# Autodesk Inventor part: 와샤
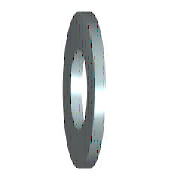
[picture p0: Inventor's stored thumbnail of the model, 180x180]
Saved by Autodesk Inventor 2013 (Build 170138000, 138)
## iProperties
IsCustomPart: 0
Created: 2009-02
Part Number: 와샤
Material: 강, 연강
Description: 평면 와셔
Document SubType Name: Modeling
Standard: KS B 1326
Designer: 한국산업디자인학원
Standards Organization: KS
Language: ko-KR
Size Designation: 5x10
Categories: <MemberInstance><Categories><Category DisplayName="조임쇠" InternalName="e4da775c-781d-43d5-af7c-5136215cf5a6" Mnemonic="FSTN"><Category DisplayName="와셔" InternalN
Density: 1 g/cm^3
Author: 한국산업디자인학원
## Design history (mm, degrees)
sketch "스케치"
  geometry: C1 r 8.5 at (0, 0); C2 r 2.65 at (0, 0); 1 further point
  constraints: 2 centre point, 2 coincident
  dimensions: "d0" = 5.3 diameter of C2 (= SD1); "d1" = 17 diameter of C1 (computed from SD2)
extrude "본체" new body sketch "스케치" distance "d2" = 1 (= SD); taper "d3" = 0 deg
workaxis "Work Axis1"
workplane "Work Plane1"
body "Solid1"
other parameters: "SD1" = 5.3 [user parameter; used in 1 equation term], "SD" = 1 [user parameter; used in 1 equation term], "d4" = 0, "d5" = 0, "d6" = 0, "d7" = 0, "NND" = 5 [user parameter]
